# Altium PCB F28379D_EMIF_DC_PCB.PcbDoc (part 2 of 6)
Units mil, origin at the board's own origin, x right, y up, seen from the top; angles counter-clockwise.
Board outline 3000 x 1480 mil, 6 copper layers (Top Layer, Signal Layer 1, Signal Layer 2, Signal Layer 3, Signal Layer 4, Bottom Layer), stack 61.4 mil thick; 51 components, 68 nets, 414 pads, 205 vias.
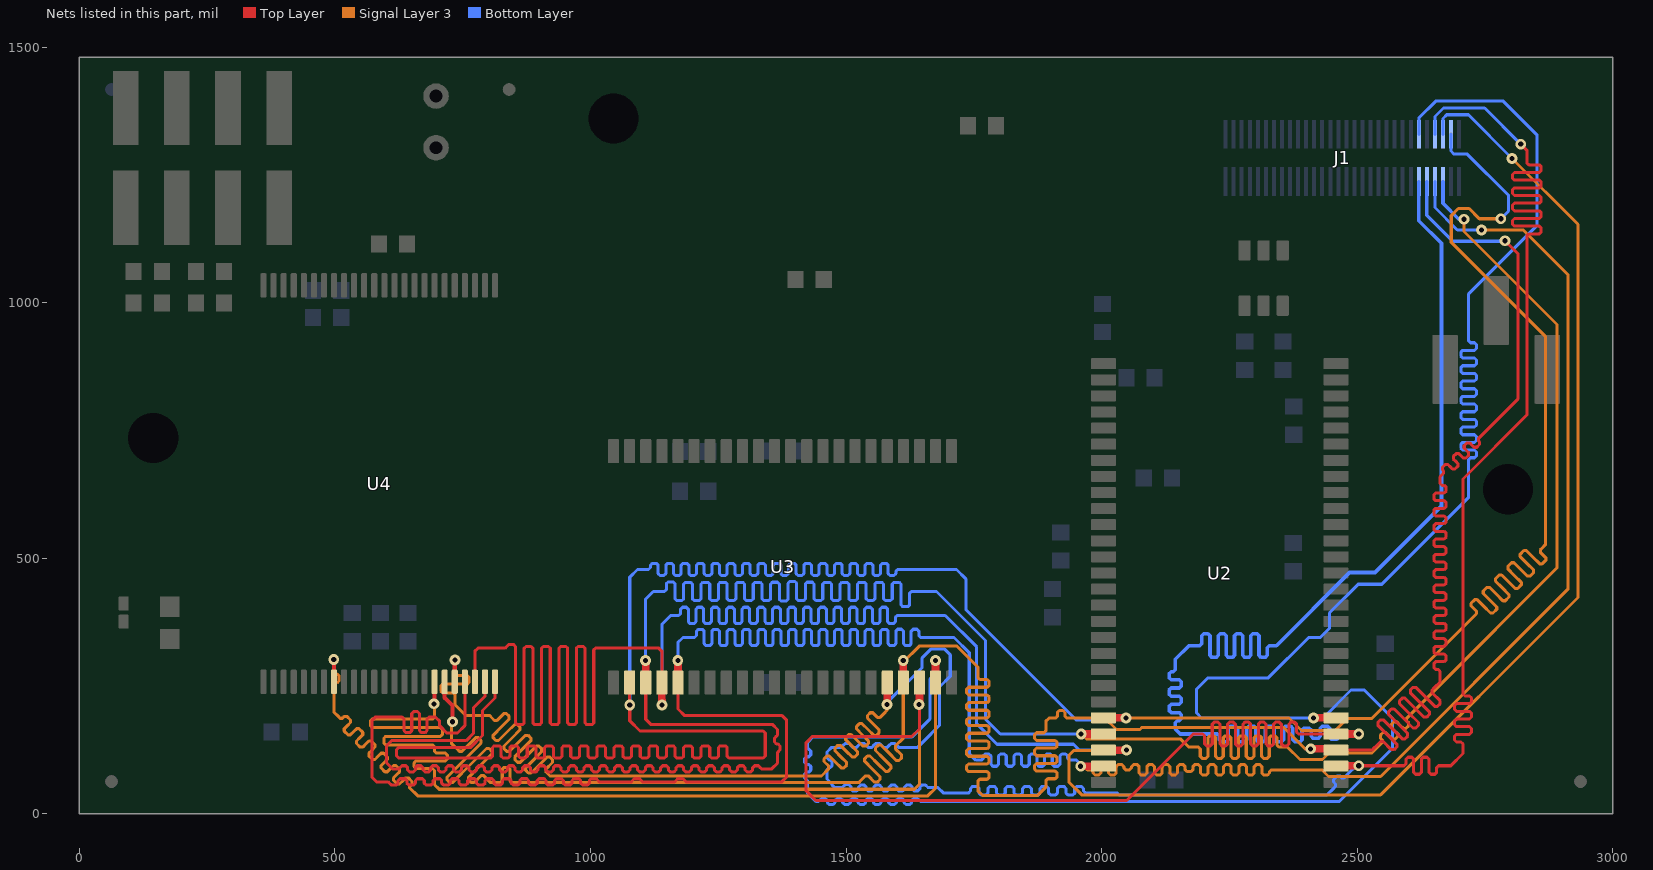
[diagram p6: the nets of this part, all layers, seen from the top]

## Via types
v1: diameter 21, hole 10, Top Layer to Bottom Layer, 204 vias
v2: diameter 20, hole 10, Top Layer to Bottom Layer, 1 vias

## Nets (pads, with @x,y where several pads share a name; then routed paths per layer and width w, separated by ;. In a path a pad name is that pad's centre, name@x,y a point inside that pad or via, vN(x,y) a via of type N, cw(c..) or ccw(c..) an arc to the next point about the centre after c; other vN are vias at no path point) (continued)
EM_A0: J1.4@2683.6,1329.26 U2.23 U3.2 U4.24 | length 6472.3
  Top Layer w6: U4.24@813.38,258.2 813.38,226.38 789,202 789,153 766,130 625,130 620.5,125.5 620.5,113.5 625,109 800,109 805.1,109 808.5,112.4 808.5,129.6 811.9,133 822.1,133 825.5,129.6 825.5,112.4 828.9,109 839.1,109 842.5,112.4 842.5,129.6 845.9,133 856.1,133 859.5,129.6 859.5,112.4 862.9,109 873.1,109 876.5,112.4 876.5,129.6 879.9,133 890.1,133 893.5,129.6 893.5,112.4 896.9,109 907.1,109 910.5,112.4 910.5,129.6 913.9,133 924.1,133 927.5,129.6 927.5,112.4 930.9,109 941.1,109 944.5,112.4 944.5,129.6 947.9,133 958.1,133 961.5,129.6 961.5,112.4 964.9,109 975.1,109 978.5,112.4 978.5,129.6 981.9,133 992.1,133 995.5,129.6 995.5,112.4 998.9,109 1009.1,109 1012.5,112.4 1012.5,129.6 1015.9,133 1026.1,133 1029.5,129.6 1029.5,112.4 1032.9,109 1043.1,109 1046.5,112.4 1046.5,129.6 1049.9,133 1060.1,133 1063.5,129.6 1063.5,112.4 1066.9,109 1077.1,109 1080.5,112.4 1080.5,129.6 1083.9,133 1094.1,133 1097.5,129.6 1097.5,112.4 1100.9,109 1111.1,109 1114.5,112.4 1114.5,129.6 1117.9,133 1128.1,133 1131.5,129.6 1131.5,112.4 1134.9,109 1145.1,109 1148.5,112.4 1148.5,129.6 1151.9,133 1162.1,133 1165.5,129.6 1165.5,112.4 1168.9,109 1179.1,109 1182.5,112.4 1182.5,129.6 1185.9,133 1196.1,133 1199.5,129.6 1199.5,112.4 1202.9,109 1213.1,109 1216.5,112.4 1216.5,129.6 1219.9,133 1230.1,133 1233.5,129.6 1233.5,112.4 1236.9,109 1247.1,109 1250.5,112.4 1250.5,129.6 1253.9,133 1264.1,133 1267.5,129.6 1267.5,112.4 1270.9,109 1271,109 1338,109 1342,113 1342,158 1338,162 1097,162 1077,182 v1(1077,213) v1@1077,217 ; v1@1076.79,217 U3.2@1076.79,256.62
  Top Layer w15: U2.23@2003.64,187.54 v1(2047.54,187.54)
  Signal Layer 3 w6: v1(2047.54,187.54) 2366.46,187.54 2391,163 2457,163 2480,186 2528,186 2702.5,360.5 2733.38,391.38 2733.38,396.19 2722.62,406.94 2722.62,411.75 2729.83,418.96 2734.64,418.96 2747.8,405.8 2760.96,392.64 2765.77,392.64 2772.99,399.85 2772.99,404.66 2759.82,417.82 2746.66,430.99 2746.66,435.79 2753.87,443.01 2758.68,443.01 2771.84,429.84 2785.01,416.68 2789.81,416.68 2797.03,423.89 2797.03,428.7 2783.86,441.86 2770.7,455.03 2770.7,459.84 2777.91,467.05 2782.72,467.05 2795.89,453.89 2809.05,440.72 2813.86,440.72 2821.07,447.94 2821.07,452.74 2807.91,465.91 2794.74,479.07 2794.74,483.88 2801.96,491.09 2806.76,491.09 2819.93,477.93 2833.09,464.77 2837.9,464.77 2845.11,471.98 2845.11,476.79 2831.95,489.95 2818.79,503.11 2818.79,507.92 2826,515.13 2830.81,515.13 2843.97,501.97 2857.13,488.81 2861.94,488.81 2869.15,496.02 2869.15,500.83 2858.39,511.59 2858.39,516.39 2862,520 2868,526 2868,934 2684,1118 2684,1170 2698,1184 2719,1184 2739,1164 v1(2781,1164)
  Bottom Layer w6: v1@1077,222 1077,463 1092,478 1110,478 1113.75,478 1117.5,481.75 1117.5,486.25 1121.25,490 1128.75,490 1132.5,486.25 1132.5,478 1132.5,469.75 1136.25,466 1143.75,466 1147.5,469.75 1147.5,478 1147.5,486.25 1151.25,490 1158.75,490 1162.5,486.25 1162.5,478 1162.5,469.75 1166.25,466 1173.75,466 1177.5,469.75 1177.5,478 1177.5,486.25 1181.25,490 1188.75,490 1192.5,486.25 1192.5,478 1192.5,469.75 1196.25,466 1203.75,466 1207.5,469.75 1207.5,478 1207.5,486.25 1211.25,490 1218.75,490 1222.5,486.25 1222.5,478 1222.5,469.75 1226.25,466 1233.75,466 1237.5,469.75 1237.5,478 1237.5,486.25 1241.25,490 1248.75,490 1252.5,486.25 1252.5,478 1252.5,469.75 1256.25,466 1263.75,466 1267.5,469.75 1267.5,478 1267.5,486.25 1271.25,490 1278.75,490 1282.5,486.25 1282.5,478 1282.5,469.75 1286.25,466 1293.75,466 1297.5,469.75 1297.5,478 1297.5,486.25 1301.25,490 1308.75,490 1312.5,486.25 1312.5,478 1312.5,469.75 1316.25,466 1323.75,466 1327.5,469.75 1327.5,478 1327.5,486.25 1331.25,490 1338.75,490 1342.5,486.25 1342.5,478 1342.5,469.75 1346.25,466 1353.75,466 1357.5,469.75 1357.5,478 1357.5,486.25 1361.25,490 1368.75,490 1372.5,486.25 1372.5,478 1372.5,469.75 1376.25,466 1383.75,466 1387.5,469.75 1387.5,478 1387.5,486.25 1391.25,490 1398.75,490 1402.5,486.25 1402.5,478 1402.5,469.75 1406.25,466 1413.75,466 1417.5,469.75 1417.5,478 1417.5,486.25 1421.25,490 1428.75,490 1432.5,486.25 1432.5,478 1432.5,469.75 1436.25,466 1443.75,466 1447.5,469.75 1447.5,478 1447.5,486.25 1451.25,490 1458.75,490 1462.5,486.25 1462.5,478 1462.5,469.75 1466.25,466 1473.75,466 1477.5,469.75 1477.5,478 1477.5,486.25 1481.25,490 1488.75,490 1492.5,486.25 1492.5,478 1492.5,469.75 1496.25,466 1503.75,466 1507.5,469.75 1507.5,478 1507.5,486.25 1511.25,490 1518.75,490 1522.5,486.25 1522.5,478 1522.5,469.75 1526.25,466 1533.75,466 1537.5,469.75 1537.5,478 1537.5,486.25 1541.25,490 1548.75,490 1552.5,486.25 1552.5,478 1552.5,469.75 1556.25,466 1563.75,466 1567.5,469.75 1567.5,478 1567.5,486.25 1571.25,490 1578.75,490 1582.5,486.25 1582.5,478 1582.5,469.75 1586.25,466 1593.75,466 1597.5,469.75 1597.5,474.25 1601.25,478 1665,478 1716,478 1734.5,459.5 1734.5,399.5 1950,184 1985,184 1988.54,187.54 v1(2047.54,187.54) ; J1.4@2683.6,1329.26 2683.6,1296.4 2689.5,1290.5 2715.5,1290.5 2796,1210 2796,1179 v1(2781,1164)
EM_A1: J1.5@2667.85,1236.74 U2.24 U3.3 U4.23 | length 6474.8
  Top Layer w6: U4.23@793.69,258.2 793.69,229.69 771,207 771,157 757,143 611,143 601,133 601,100 613,88 620,88 625.25,88 627.5,90.25 631.25,94 638.75,94 642.5,90.25 642.5,88 642.5,85.75 646.25,82 653.75,82 657.5,85.75 657.5,88 657.5,90.25 661.25,94 668.75,94 672.5,90.25 672.5,88 672.5,85.75 676.25,82 683.75,82 687.5,85.75 687.5,88 687.5,90.25 691.25,94 698.75,94 702.5,90.25 702.5,88 702.5,85.75 706.25,82 713.75,82 717.5,85.75 717.5,88 717.5,90.25 721.25,94 728.75,94 732.5,90.25 732.5,88 732.5,85.75 736.25,82 743.75,82 747.5,85.75 747.5,88 747.5,90.25 751.25,94 758.75,94 762.5,90.25 762.5,88 762.5,85.75 766.25,82 773.75,82 777.5,85.75 777.5,88 777.5,90.25 781.25,94 788.75,94 792.5,90.25 792.5,88 792.5,85.75 796.25,82 803.75,82 807.5,85.75 807.5,88 807.5,90.25 811.25,94 818.75,94 822.5,90.25 822.5,88 822.5,85.75 826.25,82 833.75,82 837.5,85.75 837.5,88 837.5,90.25 841.25,94 848.75,94 852.5,90.25 852.5,88 852.5,85.75 856.25,82 863.75,82 867.5,85.75 867.5,88 867.5,90.25 871.25,94 878.75,94 882.5,90.25 882.5,88 882.5,85.75 886.25,82 893.75,82 897.5,85.75 897.5,88 897.5,90.25 901.25,94 908.75,94 912.5,90.25 912.5,88 912.5,85.75 916.25,82 923.75,82 927.5,85.75 927.5,88 927.5,90.25 931.25,94 938.75,94 942.5,90.25 942.5,88 942.5,85.75 946.25,82 953.75,82 957.5,85.75 957.5,88 957.5,90.25 961.25,94 968.75,94 972.5,90.25 972.5,88 972.5,85.75 976.25,82 983.75,82 987.5,85.75 987.5,88 987.5,90.25 991.25,94 998.75,94 1002.5,90.25 1002.5,88 1002.5,85.75 1006.25,82 1013.75,82 1017.5,85.75 1017.5,88 1017.5,90.25 1021.25,94 1028.75,94 1032.5,90.25 1032.5,88 1032.5,85.75 1036.25,82 1043.75,82 1047.5,85.75 1047.5,88 1047.5,90.25 1051.25,94 1058.75,94 1062.5,90.25 1062.5,88 1062.5,85.75 1066.25,82 1073.75,82 1077.5,85.75 1077.5,88 1077.5,90.25 1081.25,94 1088.75,94 1092.5,90.25 1092.5,88 1092.5,85.75 1096.25,82 1103.75,82 1107.5,85.75 1107.5,88 1107.5,90.25 1111.25,94 1118.75,94 1122.5,90.25 1122.5,88 1122.5,85.75 1126.25,82 1133.75,82 1137.5,85.75 1137.5,88 1137.5,90.25 1141.25,94 1148.75,94 1152.5,90.25 1152.5,88 1152.5,85.75 1156.25,82 1163.75,82 1167.5,85.75 1167.5,88 1167.5,90.25 1171.25,94 1178.75,94 1182.5,90.25 1182.5,88 1182.5,85.75 1186.25,82 1193.75,82 1197.5,85.75 1197.5,88 1197.5,90.25 1201.25,94 1208.75,94 1212.5,90.25 1212.5,88 1212.5,85.75 1216.25,82 1223.75,82 1227.5,85.75 1227.5,88 1227.5,90.25 1231.25,94 1238.75,94 1242.5,90.25 1242.5,88 1242.5,85.75 1246.25,82 1253.75,82 1257.5,85.75 1257.5,88 1257.5,90.25 1261.25,94 1268.75,94 1272.5,90.25 1272.5,88 1272.5,85.75 1276.25,82 1283.75,82 1287.5,85.75 1287.5,88 1287.5,90.25 1291.25,94 1298.75,94 1302.5,90.25 1302.5,88 1302.5,85.75 1306.25,82 1313.75,82 1317.5,85.75 1317.5,88 1317.5,90.25 1321.25,94 1328.75,94 1332.5,90.25 1334.75,88 1347.5,88 1355,88 1366,99 1366,106.5 1366,120.25 1367.25,121.5 1371,125.25 1371,132.75 1367.25,136.5 1366,136.5 1363.75,136.5 1360,140.25 1360,147.75 1363.75,151.5 1366,153.75 1366,165 1356,175 1348.5,175 1333.5,175 1321,175 1118,175 1108.28,184.72 U3.3@1108.28,256.62
  Top Layer w15: U3.3@1108.28,256.62 v1@1108.28,290.72 ; v1@1961.96,156.04 U2.24@2003.64,156.04
  Signal Layer 3 w6: v1@1961.96,156.04 1972,146 2155.04,146 2170.52,130.52 2178.02,130.52 2189.27,130.52 2193.02,126.77 2193.02,112.27 2196.77,108.52 2204.27,108.52 2208.02,112.27 2208.02,130.52 2208.02,148.77 2211.77,152.52 2219.27,152.52 2223.02,148.77 2223.02,130.52 2223.02,112.27 2226.77,108.52 2234.27,108.52 2238.02,112.27 2238.02,130.52 2238.02,148.77 2241.77,152.52 2249.27,152.52 2253.02,148.77 2253.02,130.52 2253.02,112.27 2256.77,108.52 2264.27,108.52 2268.02,112.27 2268.02,130.52 2268.02,148.77 2271.77,152.52 2279.27,152.52 2283.02,148.77 2283.02,130.52 2283.02,112.27 2286.77,108.52 2294.27,108.52 2298.02,112.27 2298.02,130.52 2298.02,148.77 2301.77,152.52 2309.27,152.52 2313.02,148.77 2313.02,130.52 2313.02,112.27 2316.77,108.52 2324.27,108.52 2328.02,112.27 2328.02,130.52 2328.02,148.77 2331.77,152.52 2339.27,152.52 2343.02,148.77 2343.02,134.27 2346.77,130.52 2363.48,130.52 2388,106 2432,106 2445,119 2529,119 2546.5,136.5 2549.15,139.15 2549.15,144.45 2545.37,148.24 2545.37,153.54 2550.67,158.85 2555.97,158.85 2562.41,152.41 2568.85,145.97 2574.15,145.97 2579.45,151.28 2579.45,156.58 2573.02,163.02 2566.58,169.45 2566.58,174.76 2571.88,180.06 2577.19,180.06 2583.62,173.62 2590.06,167.19 2595.36,167.19 2600.67,172.49 2600.67,177.79 2596.88,181.58 2596.88,186.88 2651.5,241.5 2891,481 2891,957 2709,1139 v1(2709,1163) v1@2709,1164
  Bottom Layer w6: v1@1108,297 v1(1108,300) 1108,420 1123,435 1140,435 1145.1,435 1148.5,438.4 1148.5,450.01 1151.9,453.41 1162.1,453.41 1165.5,450.01 1165.5,435 1165.5,420.61 1168.9,417.21 1179.1,417.21 1182.5,420.61 1182.5,435 1182.5,449.33 1185.9,452.73 1196.1,452.73 1199.5,449.33 1199.5,435 1199.5,420.66 1202.9,417.26 1213.1,417.26 1216.5,420.66 1216.5,435 1216.5,449.33 1219.9,452.73 1230.1,452.73 1233.5,449.33 1233.5,435 1233.5,420.66 1236.9,417.26 1247.1,417.26 1250.5,420.66 1250.5,435 1250.5,449.33 1253.9,452.73 1264.1,452.73 1267.5,449.33 1267.5,435 1267.5,420.66 1270.9,417.26 1281.1,417.26 1284.5,420.66 1284.5,435 1284.5,449.33 1287.9,452.73 1298.1,452.73 1301.5,449.33 1301.5,435 1301.5,420.66 1304.9,417.26 1315.1,417.26 1318.5,420.66 1318.5,435 1318.5,449.33 1321.9,452.73 1332.1,452.73 1335.5,449.33 1335.5,435 1335.5,420.61 1338.9,417.21 1349.1,417.21 1352.5,420.61 1352.5,435 1352.5,449.51 1355.9,452.91 1366.1,452.91 1369.5,449.51 1369.5,435 1369.5,419.59 1372.9,416.19 1383.1,416.19 1386.5,419.59 1386.5,435 1386.5,450.88 1389.9,454.28 1400.1,454.28 1403.5,450.88 1403.5,435 1403.5,420.27 1406.9,416.87 1417.1,416.87 1420.5,420.27 1420.5,435 1420.5,449.51 1423.9,452.91 1434.1,452.91 1437.5,449.51 1437.5,435 1437.5,420.66 1440.9,417.26 1451.1,417.26 1454.5,420.66 1454.5,435 1454.5,449.33 1457.9,452.73 1468.1,452.73 1471.5,449.33 1471.5,435 1471.5,420.66 1474.9,417.26 1485.1,417.26 1488.5,420.66 1488.5,435 1488.5,449.33 1491.9,452.73 1502.1,452.73 1505.5,449.33 1505.5,435 1505.5,420.66 1508.9,417.26 1519.1,417.26 1522.5,420.66 1522.5,435 1522.5,449.33 1525.9,452.73 1536.1,452.73 1539.5,449.33 1539.5,435 1539.5,420.66 1542.9,417.26 1553.1,417.26 1556.5,420.66 1556.5,435 1556.5,449.33 1559.9,452.73 1570.1,452.73 1573.5,449.33 1573.5,435 1573.5,420.66 1576.9,417.26 1587.1,417.26 1590.5,420.66 1590.5,435 1590.5,449.33 1593.9,452.73 1604.1,452.73 1607.5,449.33 1607.5,435 1607.5,408.67 1610.9,405.27 1621.1,405.27 1624.5,408.67 1624.5,431.6 1627.9,435 1644,435 1677,435 1773,339 1773,185 1801.96,156.04 v1(1959.96,156.04) v1@1961.96,156.04
  Bottom Layer w7: J1.5@2667.85,1236.74 2667.85,1194.15 2698,1164 v1@2709,1164
EM_A2: J1.6@2667.85,1329.26 U2.25 U3.4 U4.22 | length 6534.8
  Top Layer w6: U4.22@774.01,258.2 774.01,318.01 780,324 828,324 833.1,324 836.5,327.4 839.9,330.8 850.1,330.8 853.5,327.4 853.5,324 853.5,177.82 856.9,174.42 867.1,174.42 870.5,177.82 870.5,324 873.9,327.4 884.1,327.4 887.5,324 887.5,177.82 890.9,174.42 901.1,174.42 904.5,177.82 904.5,324 907.9,327.4 918.1,327.4 921.5,324 921.5,177.82 924.9,174.42 935.1,174.42 938.5,177.82 938.5,324 941.9,327.4 952.1,327.4 955.5,324 955.5,177.82 958.9,174.42 969.1,174.42 972.5,177.82 972.5,324 975.9,327.4 986.1,327.4 989.5,324 989.5,177.82 992.9,174.42 1003.1,174.42 1006.5,177.82 1006.5,320.6 1009.9,324 1035,324 1133.78,324 1139.78,318 U3.4@1139.78,256.62
  Top Layer w15: U3.4@1139.78,256.62 1139.78,222.22 v1@1140,222 ; U2.25@2003.64,124.54 v1@2044.54,124.54
  Signal Layer 3 w6: v1@2044.54,124.54 2044,124 1946,124 1936,114 1936,62 1961,37 2546,37 2932,423 2932,1153 v1(2803,1282) ; v1@2800,1280 v1@2800.5,1279.5
  Bottom Layer w6: v1@1140,222 1140,371 1157,388 1169,388 1172.75,388 1176.5,391.75 1176.5,400.24 1180.25,403.99 1187.75,403.99 1191.5,400.24 1191.5,388 1191.5,375.76 1195.25,372.01 1202.75,372.01 1206.5,375.76 1206.5,388 1206.5,400.24 1210.25,403.99 1217.75,403.99 1221.5,400.24 1221.5,388 1221.5,375.76 1225.25,372.01 1232.75,372.01 1236.5,375.76 1236.5,388 1236.5,400.24 1240.25,403.99 1247.75,403.99 1251.5,400.24 1251.5,388 1251.5,375.76 1255.25,372.01 1262.75,372.01 1266.5,375.76 1266.5,388 1266.5,400.24 1270.25,403.99 1277.75,403.99 1281.5,400.24 1281.5,388 1281.5,375.76 1285.25,372.01 1292.75,372.01 1296.5,375.76 1296.5,388 1296.5,400.24 1300.25,403.99 1307.75,403.99 1311.5,400.24 1311.5,388 1311.5,375.76 1315.25,372.01 1322.75,372.01 1326.5,375.76 1326.5,388 1326.5,400.24 1330.25,403.99 1337.75,403.99 1341.5,400.24 1341.5,388 1341.5,375.76 1345.25,372.01 1352.75,372.01 1356.5,375.76 1356.5,388 1356.5,400.24 1360.25,403.99 1367.75,403.99 1371.5,400.24 1371.5,388 1371.5,375.76 1375.25,372.01 1382.75,372.01 1386.5,375.76 1386.5,388 1386.5,400.24 1390.25,403.99 1397.75,403.99 1401.5,400.24 1401.5,388 1401.5,375.76 1405.25,372.01 1412.75,372.01 1416.5,375.76 1416.5,388 1416.5,400.24 1420.25,403.99 1427.75,403.99 1431.5,400.24 1431.5,388 1431.5,375.76 1435.25,372.01 1442.75,372.01 1446.5,375.76 1446.5,388 1446.5,400.24 1450.25,403.99 1457.75,403.99 1461.5,400.24 1461.5,388 1461.5,375.76 1465.25,372.01 1472.75,372.01 1476.5,375.76 1476.5,388 1476.5,400.24 1480.25,403.99 1487.75,403.99 1491.5,400.24 1491.5,388 1491.5,375.76 1495.25,372.01 1502.75,372.01 1506.5,375.76 1506.5,388 1506.5,400.24 1510.25,403.99 1517.75,403.99 1521.5,400.24 1521.5,388 1521.5,375.76 1525.25,372.01 1532.75,372.01 1536.5,375.76 1536.5,388 1536.5,400.24 1540.25,403.99 1547.75,403.99 1551.5,400.24 1551.5,388 1551.5,375.76 1555.25,372.01 1562.75,372.01 1566.5,375.76 1566.5,388 1566.5,400.24 1570.25,403.99 1577.75,403.99 1581.5,400.24 1581.5,388 1581.5,375.76 1585.25,372.01 1592.75,372.01 1596.5,375.76 1596.5,384.25 1600.25,388 1679,388 1694,388 1755.5,326.5 1755.5,176 1795.5,136 1945,136 1956.46,124.54 v1@2044.54,124.54 ; J1.6@2667.85,1329.26 2667.85,1360 2675.26,1367.41 2717.59,1367.41 v1(2803,1282)
  other v1: 2048.54,124.54 1140,213
EM_A3: J1.7@2652.1,1236.74 U2.26 U3.5 U4.21 | length 6473.9
  Top Layer w6: U4.21@754.32,258.2 754.32,172.32 740,158 719,158 705,172 705,181 697,189 688,189 684.25,189 680.5,185.25 680.5,162.51 676.75,158.76 669.25,158.76 665.5,162.51 665.5,189 665.5,196.04 661.75,199.79 654.25,199.79 650.5,196.04 650.5,189 650.5,162.51 646.75,158.76 639.25,158.76 635.5,162.51 635.5,185.25 631.75,189 579,189 573,183 573,71 581.5,62.5 590,62.5 604.4,62.5 607,59.9 610.4,56.5 620.6,56.5 624,59.9 624,62.5 624,65.1 627.4,68.5 637.6,68.5 641,65.1 641,62.5 641,59.9 644.4,56.5 654.6,56.5 658,59.9 658,62.5 658,65.1 661.4,68.5 671.6,68.5 675,65.1 675,62.5 675,59.9 678.4,56.5 688.6,56.5 692,59.9 692,62.5 692,65.1 695.4,68.5 705.6,68.5 709,65.1 709,62.5 709,59.9 712.4,56.5 722.6,56.5 726,59.9 726,62.5 726,65.1 729.4,68.5 739.6,68.5 743,65.1 743,62.5 743,59.9 746.4,56.5 756.6,56.5 760,59.9 760,62.5 760,65.1 763.4,68.5 773.6,68.5 777,65.1 777,62.5 777,59.9 780.4,56.5 790.6,56.5 794,59.9 794,62.5 794,65.1 797.4,68.5 807.6,68.5 811,65.1 811,62.5 811,59.9 814.4,56.5 824.6,56.5 828,59.9 828,62.5 828,65.1 831.4,68.5 841.6,68.5 845,65.1 845,62.5 845,59.9 848.4,56.5 858.6,56.5 862,59.9 862,62.5 862,65.1 865.4,68.5 875.6,68.5 879,65.1 879,62.5 879,59.9 882.4,56.5 892.6,56.5 896,59.9 896,62.5 896,65.1 899.4,68.5 909.6,68.5 913,65.1 913,62.5 913,59.9 916.4,56.5 926.6,56.5 930,59.9 930,62.5 930,65.1 933.4,68.5 943.6,68.5 947,65.1 947,62.5 947,59.9 950.4,56.5 960.6,56.5 964,59.9 964,62.5 964,65.1 967.4,68.5 977.6,68.5 981,65.1 981,62.5 981,59.9 984.4,56.5 994.6,56.5 998,59.9 998,62.5 998,65.1 1001.4,68.5 1011.6,68.5 1015,65.1 1017.6,62.5 1053,62.5 1074,62.5 1079.9,62.5 1082.5,65.1 1085.9,68.5 1096.1,68.5 1099.5,65.1 1102.1,62.5 1151,62.5 1159,62.5 1164.9,62.5 1167.5,65.1 1170.9,68.5 1181.1,68.5 1184.5,65.1 1187.1,62.5 1218,62.5 1374.5,62.5 1384,72 1384,183 1375,192 1184.28,192 1171.28,205 U3.5@1171.28,256.62
  Top Layer w15: v1@1171,291 1171.28,290.72 U3.5@1171.28,256.62 ; v1@1963.05,93.05 U2.26@2003.64,93.05
  Signal Layer 3 w6: v1@1963.05,93.05 v1@1964.05,92.05 ; v1@1965.05,93.05 1972.1,86 1979.75,86 1983.5,82.25 1983.5,79.75 1987.25,76 1994.75,76 1998.5,79.75 1998.5,86 1998.5,92.25 2002.25,96 2009.75,96 2013.5,92.25 2013.5,86 2013.5,79.75 2017.25,76 2024.75,76 2028.5,79.75 2028.5,86 2028.5,92.25 2032.25,96 2039.75,96 2043.5,92.25 2043.5,89.75 2047.25,86 2054.75,86 2058.5,89.75 2058.5,92.25 2062.25,96 2069.75,96 2073.5,92.25 2073.5,86 2073.5,79.75 2077.25,76 2084.75,76 2088.5,79.75 2088.5,86 2088.5,92.25 2092.25,96 2099.75,96 2103.5,92.25 2103.5,86 2103.5,79.75 2107.25,76 2114.75,76 2118.5,79.75 2118.5,86 2118.5,92.25 2122.25,96 2129.75,96 2133.5,92.25 2133.5,86 2133.5,79.75 2137.25,76 2144.75,76 2148.5,79.75 2148.5,86 2148.5,92.25 2152.25,96 2159.75,96 2163.5,92.25 2163.5,86 2166.67,82.83 2175.33,82.83 2178.5,86 2178.5,92.25 2182.25,96 2189.75,96 2193.5,92.25 2193.5,86 2193.5,79.75 2197.25,76 2204.75,76 2208.5,79.75 2208.5,86 2208.5,92.25 2212.25,96 2219.75,96 2223.5,92.25 2223.5,86 2223.5,79.75 2227.25,76 2234.75,76 2238.5,79.75 2238.5,86 2238.5,92.25 2242.25,96 2249.75,96 2253.5,92.25 2253.5,86 2253.5,79.75 2257.25,76 2264.75,76 2268.5,79.75 2268.5,86 2268.5,92.25 2272.25,96 2279.75,96 2283.5,92.25 2283.5,86 2283.5,79.75 2287.25,76 2294.75,76 2298.5,79.75 2298.5,86 2298.5,92.25 2302.25,96 2309.75,96 2313.5,92.25 2313.5,86 2313.5,79.75 2317.25,76 2324.75,76 2328.5,79.75 2328.5,82.25 2332.25,86 2336,86 2431.05,86 2444.05,73 2545.95,73 2912,439.05 2912,1055 2825,1142 v1(2743,1142)
  Bottom Layer w6: v1@1171,297 v1(1171,300) 1171,335 1181,345 1200,345 1203.75,345 1207.5,348.75 1207.5,357.01 1211.25,360.76 1218.75,360.76 1222.5,357.01 1222.5,345 1222.5,332.75 1226.25,329 1233.75,329 1237.5,332.75 1237.5,345 1237.5,357.01 1241.25,360.76 1248.75,360.76 1252.5,357.01 1252.5,345 1252.5,332.75 1256.25,329 1263.75,329 1267.5,332.75 1267.5,345 1267.5,357.01 1271.25,360.76 1278.75,360.76 1282.5,357.01 1282.5,345 1282.5,332.75 1286.25,329 1293.75,329 1297.5,332.75 1297.5,345 1297.5,357.01 1301.25,360.76 1308.75,360.76 1312.5,357.01 1312.5,345 1312.5,332.75 1316.25,329 1323.75,329 1327.5,332.75 1327.5,345 1327.5,357.01 1331.25,360.76 1338.75,360.76 1342.5,357.01 1342.5,345 1342.5,332.75 1346.25,329 1353.75,329 1357.5,332.75 1357.5,345 1357.5,357.01 1361.25,360.76 1368.75,360.76 1372.5,357.01 1372.5,345 1372.5,332.75 1376.25,329 1383.75,329 1387.5,332.75 1387.5,345 1387.5,357.01 1391.25,360.76 1398.75,360.76 1402.5,357.01 1402.5,345 1402.5,332.75 1406.25,329 1413.75,329 1417.5,332.75 1417.5,345 1417.5,357.01 1421.25,360.76 1428.75,360.76 1432.5,357.01 1432.5,345 1432.5,332.75 1436.25,329 1443.75,329 1447.5,332.75 1447.5,345 1447.5,357.01 1451.25,360.76 1458.75,360.76 1462.5,357.01 1462.5,345 1462.5,332.75 1466.25,329 1473.75,329 1477.5,332.75 1477.5,345 1477.5,357.01 1481.25,360.76 1488.75,360.76 1492.5,357.01 1492.5,345 1492.5,332.75 1496.25,329 1503.75,329 1507.5,332.75 1507.5,345 1507.5,357.01 1511.25,360.76 1518.75,360.76 1522.5,357.01 1522.5,345 1522.5,332.75 1526.25,329 1533.75,329 1537.5,332.75 1537.5,345 1537.5,357.01 1541.25,360.76 1548.75,360.76 1552.5,357.01 1552.5,345 1552.5,332.75 1556.25,329 1563.75,329 1567.5,332.75 1567.5,345 1567.5,357.01 1571.25,360.76 1578.75,360.76 1582.5,357.01 1582.5,345 1582.5,332.75 1586.25,329 1593.75,329 1597.5,332.75 1597.5,345 1597.5,357.25 1601.25,361 1608.75,361 1612.5,357.25 1612.5,345 1612.5,332.75 1616.25,329 1623.75,329 1627.5,332.75 1627.5,345 1627.5,357.25 1631.25,361 1638.75,361 1642.5,357.25 1642.5,348.75 1646.25,345 1693,345 1711.1,345 1741.1,315 1741.1,117.9 1754,105 1761,105 1764.75,105 1768.5,108.75 1768.5,113.25 1772.25,117 1779.75,117 1783.5,113.25 1783.5,105 1783.5,96.75 1787.25,93 1794.75,93 1798.5,96.75 1798.5,105 1798.5,113.25 1802.25,117 1809.75,117 1813.5,113.25 1813.5,105 1813.5,96.75 1817.25,93 1824.75,93 1828.5,96.75 1828.5,105 1828.5,113.25 1832.25,117 1839.75,117 1843.5,113.25 1843.5,105 1843.5,96.75 1847.25,93 1854.75,93 1858.5,96.75 1858.5,105 1858.5,113.25 1862.25,117 1869.75,117 1873.5,113.25 1873.5,105 1873.5,96.75 1877.25,93 1884.75,93 1888.5,96.75 1888.5,105 1888.5,113.25 1892.25,117 1899.75,117 1903.5,113.25 1903.5,105 1903.5,96.75 1907.25,93 1914.75,93 1918.5,96.75 1918.5,105 1918.5,113.25 1922.25,117 1929.75,117 1933.5,113.25 1933.5,108.75 1937.25,105 1951,105 1951.1,105 v1@1963.05,93.05 ; J1.7@2652.1,1236.74 2652.1,1185.9 2696,1142 v1(2743,1142)
  other v1: 1959.05,93.05
EM_A4: J1.8@2652.1,1329.26 U2.29 U3.18 U4.20 | length 6436.5
  Top Layer w6: v1@2498,94 v1(2503,94) 2588,94 2591.75,94 2595.5,97.75 2595.5,106.87 2599.25,110.62 2606.75,110.62 2610.5,106.87 2610.5,94 2610.5,81.13 2614.25,77.38 2621.75,77.38 2625.5,81.13 2625.5,94 2625.5,106.87 2629.25,110.62 2636.75,110.62 2640.5,106.87 2640.5,94 2640.5,81.13 2644.25,77.38 2651.75,77.38 2655.5,81.13 2655.5,90.25 2659.25,94 2670.5,94 2683,94 2707,118 2707,125.5 2707,136.75 2703.25,140.5 2694.13,140.5 2690.38,144.25 2690.38,151.75 2694.13,155.5 2707,155.5 2719.87,155.5 2723.62,159.25 2723.62,166.75 2719.87,170.5 2707,170.5 2694.13,170.5 2690.38,174.25 2690.38,181.75 2694.13,185.5 2707,185.5 2719.87,185.5 2723.62,189.25 2723.62,196.75 2719.87,200.5 2707,200.5 2694.13,200.5 2690.38,204.25 2690.38,211.75 2694.13,215.5 2707,215.5 2719.87,215.5 2723.62,219.25 2723.62,226.75 2719.87,230.5 2710.75,230.5 2707,234.25 2707,276 2707,655 2832,780 2832,1123 2832,1130.75 2835.75,1134.5 2856.25,1134.5 2860,1138.25 2860,1145.75 2856.25,1149.5 2832,1149.5 2807.75,1149.5 2804,1153.25 2804,1160.75 2807.75,1164.5 2832,1164.5 2856.25,1164.5 2860,1168.25 2860,1175.75 2856.25,1179.5 2832,1179.5 2807.75,1179.5 2804,1183.25 2804,1190.75 2807.75,1194.5 2832,1194.5 2856.25,1194.5 2860,1198.25 2860,1205.75 2856.25,1209.5 2832,1209.5 2807.75,1209.5 2804,1213.25 2804,1220.75 2807.75,1224.5 2832,1224.5 2856.25,1224.5 2860,1228.25 2860,1235.75 2856.25,1239.5 2832,1239.5 2807.75,1239.5 2804,1243.25 2804,1250.75 2807.75,1254.5 2832,1254.5 2856.25,1254.5 2860,1258.25 2860,1265.75 2856.25,1269.5 2835.75,1269.5 2832,1273.25 2832,1277 2832,1298 v1(2820,1310)
  Top Layer w8: U4.20@734.64,258.2 734.64,297.64 v1@735,298
  Top Layer w15: v1@1580.72,222.72 U3.18@1580.72,256.62 ; U2.29@2458.36,93.05 2460.41,91 2463.41,94 v1@2498,94
  Signal Layer 3 w6: v1@735,298 735,279 735,273.9 738.4,270.5 759.07,270.5 762.47,267.1 762.47,256.9 759.07,253.5 735,253.5 710.93,253.5 707.53,250.1 707.53,239.9 710.93,236.5 731.6,236.5 735,233.1 735,220 735,213 755.5,192.5 802.5,192.5 809.5,185.5 812.15,182.85 817.45,182.85 830.54,195.93 835.84,195.93 841.14,190.63 841.14,185.32 825.41,169.59 809.68,153.86 809.68,148.55 814.98,143.25 820.28,143.25 836.02,158.98 851.75,174.72 857.05,174.72 862.36,169.41 862.36,164.11 846.62,148.38 830.89,132.64 830.89,127.34 836.19,122.04 841.5,122.04 857.23,137.77 872.96,153.5 878.27,153.5 883.57,148.2 883.57,142.9 867.84,127.16 852.1,111.43 852.1,106.13 857.41,100.82 862.71,100.82 878.44,116.56 894.18,132.29 899.48,132.29 904.78,126.99 904.78,121.68 889.05,105.95 873.32,90.22 873.32,84.91 878.62,79.61 883.92,79.61 899.66,95.34 915.39,111.08 920.69,111.08 926,105.77 926,100.47 912.91,87.39 912.91,82.09 915,80 921,74 1431,74 1444.5,74 1452,74 1465.98,87.98 1465.98,93.28 1457.14,102.12 1457.14,107.42 1462.44,112.73 1467.75,112.73 1479.24,101.24 1490.73,89.75 1496.03,89.75 1501.33,95.05 1501.33,100.35 1489.84,111.84 1478.35,123.33 1478.35,128.64 1483.66,133.94 1488.96,133.94 1500.45,122.45 1511.94,110.96 1517.24,110.96 1522.55,116.26 1522.55,121.57 1511.06,133.06 1499.57,144.55 1499.57,149.85 1504.87,155.15 1510.17,155.15 1521.66,143.66 1533.15,132.17 1538.46,132.17 1543.76,137.48 1543.76,142.78 1532.27,154.27 1520.78,165.76 1520.78,171.06 1526.08,176.37 1531.39,176.37 1542.88,164.88 1554.37,153.39 1559.67,153.39 1564.97,158.69 1564.97,163.99 1553.48,175.48 1541.99,186.97 1541.99,192.28 1547.3,197.58 1552.6,197.58 1561.44,188.74 1566.74,188.74 1574.7,196.7 1580,202 v1(1580,214) v1@1580,217
  Bottom Layer w6: v1@1580,217 1649,286 1649,305 1666,322 1693,322 1704,311 1704,269 1683,248 1683,173 1651,141 1645.3,135.3 1640,130 1629.5,130 1614.5,130 1603.25,130 1599.5,133.75 1595.75,137.5 1588.25,137.5 1584.5,133.75 1580.75,130 1573.25,130 1569.5,133.75 1565.75,137.5 1558.25,137.5 1554.5,133.75 1550.75,130 1543.25,130 1539.5,133.75 1535.75,137.5 1528.25,137.5 1524.5,133.75 1520.75,130 1513.25,130 1509.5,133.75 1505.75,137.5 1498.25,137.5 1494.5,133.75 1490.75,130 1479.5,130 1472,130 1463,121 1463,120.5 1463,109.25 1466.75,105.5 1469.25,105.5 1473,101.75 1473,94.25 1469.25,90.5 1466.75,90.5 1463,86.75 1463,75.5 1463,68 1473,58 1473,56 1478,51 1487,51 1492.25,51 1494.5,53.25 1498.25,57 1505.75,57 1509.5,53.25 1509.5,51 1509.5,48.75 1513.25,45 1520.75,45 1524.5,48.75 1524.5,51 1524.5,52.25 1528.25,56 1535.75,56 1539.5,52.25 1539.5,51 1539.5,48.75 1543.25,45 1550.75,45 1554.5,48.75 1554.5,51 1554.5,52.25 1558.25,56 1565.75,56 1569.5,52.25 1569.5,51 1569.5,48.75 1573.25,45 1580.75,45 1584.5,48.75 1584.5,51 1584.5,52.25 1588.25,56 1595.75,56 1599.5,52.25 1599.5,51 1599.5,48.75 1603.25,45 1610.75,45 1614.5,48.75 1614.5,51 1614.5,52.25 1618.25,56 1625.75,56 1629.5,52.25 1629.5,51 1629.5,48.75 1633.25,45 1640.75,45 1644.5,48.75 1644.5,51 1644.5,52.25 1648.25,56 1655.75,56 1659.5,52.25 1660.75,51 1674.5,51 1680,51 1690,41 1735,41 1740.1,41 1743.5,44.4 1743.5,49.6 1746.9,53 1757.1,53 1760.5,49.6 1760.5,41 1760.5,40.4 1763.9,37 1774.1,37 1777.5,40.4 1777.5,41 1777.5,49.6 1780.9,53 1791.1,53 1794.5,49.6 1794.5,41 1794.5,40.4 1797.9,37 1808.1,37 1811.5,40.4 1811.5,41 1811.5,49.6 1814.9,53 1825.1,53 1828.5,49.6 1828.5,41 1828.5,40.4 1831.9,37 1842.1,37 1845.5,40.4 1845.5,41 1845.5,49.6 1848.9,53 1859.1,53 1862.5,49.6 1862.5,41 1862.5,40.4 1865.9,37 1876.1,37 1879.5,40.4 1879.5,41 1879.5,49.6 1882.9,53 1893.1,53 1896.5,49.6 1896.5,41 1896.5,40.4 1899.9,37 1910.1,37 1913.5,40.4 1913.5,41 1913.5,49.6 1916.9,53 1927.1,53 1930.5,49.6 1930.5,41 1930.5,40.4 1933.9,37 1944.1,37 1947.5,40.4 1947.5,41 1947.5,49.6 1950.9,53 1961.1,53 1964.5,49.6 1964.5,44.4 1967.9,41 2019,41 2030,41 2034,37 2441,37 2454,50 2457.61,53.61 2457.61,58.41 2453.93,62.09 2453.93,66.9 2461.14,74.11 2465.95,74.11 2469.63,70.44 2474.44,70.44 2482,78 v1@2498,94 ; J1.8@2652.1,1329.26 2652.1,1364.1 2668.7,1380.7 2749.3,1380.7 v1(2820,1310)
  other v1: 735,301
EM_A5: J1.9@2636.35,1236.74 U2.30 U3.19 U4.19 | length 6400.8
  Top Layer w6: U2.30@2455.91,127 U2.30@2458.36,127 ; U2.30@2458.36,124.54 2529,124.54 2532.46,128 2537.76,133.3 2545.71,141.26 2551.02,141.26 2566.93,125.35 2572.23,125.35 2577.53,130.65 2577.53,135.95 2558.97,154.52 2540.41,173.08 2540.41,178.38 2545.71,183.68 2551.02,183.68 2569.58,165.12 2588.14,146.56 2593.44,146.56 2598.75,151.86 2598.75,157.17 2580.19,175.73 2561.62,194.29 2561.62,199.59 2566.93,204.9 2572.23,204.9 2590.79,186.34 2609.35,167.77 2614.66,167.77 2619.96,173.08 2619.96,178.38 2601.4,196.94 2582.84,215.5 2582.84,220.81 2588.14,226.11 2593.44,226.11 2612.01,207.55 2630.57,188.99 2635.87,188.99 2641.17,194.29 2641.17,199.59 2622.61,218.16 2604.05,236.72 2604.05,242.02 2609.35,247.32 2614.66,247.32 2633.22,228.76 2651.78,210.2 2657.08,210.2 2662.39,215.5 2662.39,220.81 2646.48,236.72 2646.48,242.02 2650.73,246.27 2662,257.54 2662,275 2662,278.75 2658.25,282.5 2653.75,282.5 2650,286.25 2650,293.75 2653.75,297.5 2662,297.5 2670.25,297.5 2674,301.25 2674,308.75 2670.25,312.5 2662,312.5 2653.75,312.5 2650,316.25 2650,323.75 2653.75,327.5 2662,327.5 2670.25,327.5 2674,331.25 2674,338.75 2670.25,342.5 2662,342.5 2653.75,342.5 2650,346.25 2650,353.75 2653.75,357.5 2662,357.5 2670.25,357.5 2674,361.25 2674,368.75 2670.25,372.5 2662,372.5 2653.75,372.5 2650,376.25 2650,383.75 2653.75,387.5 2662,387.5 2670.25,387.5 2674,391.25 2674,398.75 2670.25,402.5 2662,402.5 2653.75,402.5 2650,406.25 2650,413.75 2653.75,417.5 2662,417.5 2670.25,417.5 2674,421.25 2674,428.75 2670.25,432.5 2662,432.5 2653.75,432.5 2650,436.25 2650,443.75 2653.75,447.5 2662,447.5 2670.25,447.5 2674,451.25 2674,458.75 2670.25,462.5 2662,462.5 2653.75,462.5 2650,466.25 2650,473.75 2653.75,477.5 2662,477.5 2670.25,477.5 2674,481.25 2674,488.75 2670.25,492.5 2662,492.5 2653.75,492.5 2650,496.25 2650,503.75 2653.75,507.5 2662,507.5 2670.25,507.5 2674,511.25 2674,518.75 2670.25,522.5 2662,522.5 2653.75,522.5 2650,526.25 2650,533.75 2653.75,537.5 2662,537.5 2670.25,537.5 2674,541.25 2674,548.75 2670.25,552.5 2662,552.5 2653.75,552.5 2650,556.25 2650,563.75 2653.75,567.5 2662,567.5 2670.25,567.5 2674,571.25 2674,578.75 2670.25,582.5 2662,582.5 2653.75,582.5 2650,586.25 2650,593.75 2653.75,597.5 2662,597.5 2670.25,597.5 2674,601.25 2674,608.75 2670.25,612.5 2662,612.5 2653.75,612.5 2650,616.25 2650,623.75 2653.75,627.5 2662,627.5 2670.25,627.5 2674,631.25 2674,638.75 2670.25,642.5 2665.75,642.5 2662,646.25 2662,651 2662,659 2666,663 2668.65,665.65 2668.65,670.95 2667,672.6 2667,677.91 2672.31,683.21 2677.61,683.21 2681.91,678.91 2686.21,674.61 2691.51,674.61 2696.82,679.91 2696.82,685.22 2692.52,689.52 2688.22,693.82 2688.22,699.12 2693.52,704.42 2698.82,704.42 2703.12,700.12 2707.42,695.82 2712.73,695.82 2718.03,701.13 2718.03,706.43 2713.73,710.73 2709.43,715.03 2709.43,720.33 2714.73,725.64 2720.04,725.64 2724.34,721.34 2728.64,717.04 2733.94,717.04 2739.24,722.34 2739.24,727.64 2737.59,729.29 2737.59,734.59 2773,770 2815,812 2815,1095 v1(2789,1121)
  Top Layer w8: U4.19@714.95,258.2 714.95,227.05 730,212 v1(730,180) ; v1@728,179 v1@728,180
  Top Layer w15: U3.19@1612.22,256.62 v1@1612.22,291.78 ; v1(2409,127) U2.30@2455.91,127
  Signal Layer 3 w6: v1@728,179 728,138 741,125 743.65,122.35 748.95,122.35 775.46,148.85 780.76,148.85 786.07,143.55 786.07,138.25 756.91,109.09 719.42,71.6 719.42,66.3 724.73,61 730.03,61 767.52,98.48 796.67,127.64 801.98,127.64 807.28,122.34 807.28,117.03 778.12,87.88 761.85,71.61 761.85,66.3 767.15,61 772.46,61 786.08,74.62 791.38,74.62 799.34,66.66 805,61 812.5,61 823.75,61 827.5,64.75 827.5,87.12 831.25,90.87 838.75,90.87 842.5,87.12 842.5,64.75 846.25,61 852,61 1525,61 1530.3,66.3 1538.26,74.26 1543.56,74.26 1555.91,61.91 1561.21,61.91 1566.52,67.21 1566.52,72.52 1551.52,87.52 1536.52,102.52 1536.52,107.82 1541.82,113.12 1547.12,113.12 1562.12,98.12 1577.12,83.12 1582.43,83.12 1587.73,88.43 1587.73,93.73 1572.73,108.73 1557.73,123.73 1557.73,129.03 1563.03,134.34 1568.34,134.34 1583.34,119.34 1598.34,104.34 1603.64,104.34 1608.94,109.64 1608.94,114.94 1596.59,127.29 1596.59,132.59 1612,148 1612,297 1643,328 1717,328 1758,287 1758,284 1758,277.5 1758,266.25 1761.75,262.5 1776.25,262.5 1780,258.75 1780,251.25 1776.25,247.5 1758,247.5 1739.75,247.5 1736,243.75 1736,236.25 1739.75,232.5 1758,232.5 1776.25,232.5 1780,228.75 1780,221.25 1776.25,217.5 1758,217.5 1739.75,217.5 1736,213.75 1736,206.25 1739.75,202.5 1758,202.5 1776.25,202.5 1780,198.75 1780,191.25 1776.25,187.5 1758,187.5 1739.75,187.5 1736,183.75 1736,176.25 1739.75,172.5 1758,172.5 1776.25,172.5 1780,168.75 1780,161.25 1776.25,157.5 1758,157.5 1739.75,157.5 1736,153.75 1736,146.25 1739.75,142.5 1758,142.5 1776.25,142.5 1780,138.75 1780,131.25 1776.25,127.5 1758,127.5 1739.75,127.5 1736,123.75 1736,116.25 1739.75,112.5 1758,112.5 1776.25,112.5 1780,108.75 1780,101.25 1776.25,97.5 1758,97.5 1739.75,97.5 1736,93.75 1736,86.25 1739.75,82.5 1758,82.5 1776.25,82.5 1780,78.75 1780,71.25 1776.25,67.5 1761.75,67.5 1758,63.75 1758,52.5 1758,45 1767,36 1875.25,36 1891,51.75 1891,53.5 1891,64.75 1894.75,68.5 1909.25,68.5 1913,72.25 1913,79.75 1909.25,83.5 1891,83.5 1872.75,83.5 1869,87.25 1869,94.75 1872.75,98.5 1891,98.5 1909.25,98.5 1913,102.25 1913,109.75 1909.25,113.5 1891,113.5 1872.75,113.5 1869,117.25 1869,124.75 1872.75,128.5 1891,128.5 1909.25,128.5 1913,132.25 1913,139.75 1909.25,143.5 1891,143.5 1872.75,143.5 1869,147.25 1869,154.75 1872.75,158.5 1887.25,158.5 1891,162.25 1891,173.5 1891,181 1897,187 1906,187 1909.75,187 1913.5,190.75 1913.5,198.18 1917.25,201.93 1924.75,201.93 1928.5,198.18 1928.5,190.75 1932.25,187 1949,187 2007,187 2029,165 2075,165 2079,169 2356,169 2398,127 v1(2409,127)
  Bottom Layer w7: J1.9@2636.35,1236.74 2636.35,1170.65 2687,1120 2788,1120 v1(2789,1121)
  other v1: 1612,300
EM_A6: J1.11@2620.61,1236.74 U2.31 U3.20 U4.18 | length 6486.2
  Top Layer w6: v1@1643.72,216.72 1643.72,166 1628.72,151 1434,151 1422,139 1422,45 1441,26 2049,26 2179.04,156.04 2186.54,156.04 2197.79,156.04 2201.54,152.29 2201.54,136.71 2205.29,132.96 2212.79,132.96 2216.54,136.71 2216.54,156.04 2216.54,175.37 2220.29,179.12 2227.79,179.12 2231.54,175.37 2231.54,156.04 2231.54,136.71 2235.29,132.96 2242.79,132.96 2246.54,136.71 2246.54,156.04 2246.54,175.37 2250.29,179.12 2257.79,179.12 2261.54,175.37 2261.54,156.04 2261.54,136.71 2265.29,132.96 2272.79,132.96 2276.54,136.71 2276.54,156.04 2276.54,175.37 2280.29,179.12 2287.79,179.12 2291.54,175.37 2291.54,156.04 2291.54,136.71 2295.29,132.96 2302.79,132.96 2306.54,136.71 2306.54,156.04 2306.54,175.37 2310.29,179.12 2317.79,179.12 2321.54,175.37 2321.54,156.04 2321.54,136.71 2325.29,132.96 2332.79,132.96 2336.54,136.71 2336.54,156.04 2336.54,175.37 2340.29,179.12 2347.79,179.12 2351.54,175.37 2351.54,156.04 2351.54,136.71 2355.29,132.96 2362.79,132.96 2366.54,136.71 2366.54,156.04 2366.54,175.37 2370.29,179.12 2377.79,179.12 2381.54,175.37 2381.54,159.79 2385.29,156.04 2397,156.04 U2.31@2458.36,156.04
  Top Layer w8: v1(694,215) 695.27,216.27 U4.18@695.27,258.2
  Top Layer w15: v1@1643.72,216.72 U3.20@1643.72,256.62 ; U2.31@2458.36,156.04 v1@2499.04,156.04
  Signal Layer 3 w6: v1@695,218 695,200 695,188.9 691.6,185.5 573.12,185.5 569.72,182.1 569.72,171.9 573.12,168.5 695,168.5 706.88,168.5 710.28,165.1 710.28,154.9 706.88,151.5 695,151.5 599.55,151.5 596.14,148.1 596.14,137.9 599.55,134.5 691.6,134.5 695,131.1 695,126 695,122.25 698.75,118.5 716.42,118.5 720.17,114.75 720.17,107.25 716.42,103.5 695,103.5 658.95,103.5 655.2,99.75 655.2,92.25 658.95,88.5 691.25,88.5 695,84.75 695,57 704,48 1634,48 1643.72,57.72 v1@1643.72,216.72
  Bottom Layer w7: v1@2499.04,156.04 2473,156.04 2467.6,156.04 2464,152.44 2464,149.6 2460.4,146 2449.6,146 2446,149.6 2446,156.04 2446,167.44 2442.4,171.04 2431.6,171.04 2428,167.44 2428,156.04 2428,151.6 2424.4,148 2413.6,148 2410,151.6 2410,156.04 2410,164.01 2406.4,167.61 2395.6,167.61 2392,164.01 2392,156.04 2392,144.64 2388.4,141.04 2377.6,141.04 2374,144.64 2374,156.04 2374,167.44 2370.4,171.04 2359.6,171.04 2356,167.44 2356,156.04 2356,144.64 2352.4,141.04 2341.6,141.04 2338,144.64 2338,156.04 2338,167.44 2334.4,171.04 2323.6,171.04 2320,167.44 2320,156.04 2320,144.64 2316.4,141.04 2305.6,141.04 2302,144.64 2302,156.04 2302,167.44 2298.4,171.04 2287.6,171.04 2284,167.44 2284,156.04 2284,144.64 2280.4,141.04 2269.6,141.04 2266,144.64 2266,156.04 2266,167.44 2262.4,171.04 2251.6,171.04 2248,167.44 2248,156.04 2248,144.64 2244.4,141.04 2233.6,141.04 2230,144.64 2230,152.44 2226.4,156.04 2166,156.04 2153.96,156.04 2144,166 2144,178 2148,182 2152,182 2156,186 2156,194 2152,198 2144,198 2136,198 2132,202 2132,210 2136,214 2144,214 2152,214 2156,218 2156,226 2152,230 2144,230 2136,230 2132,234 2132,242 2136,246 2144,246 2152,246 2156,250 2156,258 2152,262 2144,262 2136,262 2132,266 2132,274 2136,278 2140,278 2144,282 2144,294 2144,302 2171,329 2172,329 2192,329 2196,333 2196,348.15 2200,352.15 2208,352.15 2212,348.15 2212,329 2212,309.85 2216,305.85 2224,305.85 2228,309.85 2228,329 2228,348.15 2232,352.15 2240,352.15 2244,348.15 2244,329 2244,309.85 2248,305.85 2256,305.85 2260,309.85 2260,329 2260,348.15 2264,352.15 2272,352.15 2276,348.15 2276,329 2276,309.85 2280,305.85 2288,305.85 2292,309.85 2292,329 2292,348.15 2296,352.15 2304,352.15 2308,348.15 2308,329 2308,309.85 2312,305.85 2320,305.85 2324,309.85 2324,325 2328,329 2332,329 2342,329 2485,472 2535,472 2665,602 2665,1116 2620.61,1160.39 J1.11@2620.61,1236.74
  other v1: 2503.04,156.04 1642.72,213.72
EM_A7: J1.12@2620.61,1329.26 U2.32 U3.21 U4.8 | length 6438.6
  Top Layer w8: v1@498,298 498.42,297.58 U4.8@498.42,258.2
  Top Layer w15: U3.21@1675.21,256.62 v1@1675.21,292.79 ; v1(2414.46,187.54) U2.32@2458.36,187.54
  Signal Layer 3 w6: v1@498,298 498,282 498,276.9 501.4,273.5 504.63,273.5 508.03,270.1 508.03,259.9 504.63,256.5 501.4,256.5 498,253.1 498,231 498,199 506.5,190.5 510.11,186.89 514.91,186.89 518.59,190.57 523.4,190.57 530.61,183.36 530.61,178.55 524.53,172.47 518.45,166.39 518.45,161.58 525.66,154.37 530.47,154.37 536.55,160.45 542.63,166.53 547.44,166.53 554.65,159.32 554.65,154.51 548.57,148.43 542.49,142.35 542.49,137.54 549.7,130.33 554.51,130.33 560.59,136.41 566.67,142.49 571.48,142.49 578.7,135.28 578.7,130.47 572.61,124.39 566.53,118.3 566.53,113.5 573.75,106.28 578.55,106.28 584.64,112.36 590.72,118.45 595.52,118.45 602.74,111.23 602.74,106.42 596.66,100.34 590.58,94.26 590.58,89.45 597.79,82.24 602.6,82.24 608.68,88.32 614.76,94.4 619.57,94.4 626.78,87.19 626.78,82.38 620.7,76.3 614.62,70.22 614.62,65.41 621.83,58.2 626.64,58.2 632.72,64.28 638.8,70.36 643.61,70.36 650.82,63.15 650.82,58.34 646.5,54.02 646.5,50.5 662,35 1660,35 1675.21,50.21 v1@1675.21,296.79
  Bottom Layer w6: v1@1675.21,296.79 1675.21,274.21 1664,263 1664,185 1629.5,150.5 1435.5,150.5 1425,140 1425,134 1425,128.75 1427.25,126.5 1431,122.75 1431,115.25 1427.25,111.5 1425,111.5 1422.75,111.5 1419,107.75 1419,100.25 1422.75,96.5 1425,96.5 1427.25,96.5 1431,92.75 1431,85.25 1427.25,81.5 1425,81.5 1422.75,81.5 1419,77.75 1419,70.25 1422.75,66.5 1425,64.25 1425,40 1441,24 1446.25,24 1448.5,26.25 1452.25,30 1459.75,30 1463.5,26.25 1463.5,24 1463.5,21.75 1467.25,18 1474.75,18 1478.5,21.75 1478.5,24 1478.5,26.25 1482.25,30 1489.75,30 1493.5,26.25 1493.5,24 1493.5,21.75 1497.25,18 1504.75,18 1508.5,21.75 1508.5,24 1508.5,26.25 1512.25,30 1519.75,30 1523.5,26.25 1523.5,24 1523.5,21.75 1527.25,18 1534.75,18 1538.5,21.75 1538.5,24 1538.5,26.25 1542.25,30 1549.75,30 1553.5,26.25 1553.5,24 1553.5,21.75 1557.25,18 1564.75,18 1568.5,21.75 1568.5,24 1568.5,26.25 1572.25,30 1579.75,30 1583.5,26.25 1583.5,24 1583.5,21.75 1587.25,18 1594.75,18 1598.5,21.75 1598.5,24 1598.5,26.25 1602.25,30 1609.75,30 1613.5,26.25 1613.5,24 1613.5,21.75 1617.25,18 1624.75,18 1628.5,21.75 1628.5,24 1628.5,26.25 1632.25,30 1639.75,30 1643.5,26.25 1645.75,24 1723,24 2465,24 2569,128 2569,187 2514,242 2488,242 2433.54,187.54 v1(2414.46,187.54) 2195.46,187.54 2186,197 2186,244 2208,266 2326,266 2405,345 2428,345 2446,363 2446,393 2502,449 2548,449 2718,619 2718,665 2718,692.75 2721.75,696.5 2729.58,696.5 2733.33,700.25 2733.33,707.75 2729.58,711.5 2718,711.5 2706.42,711.5 2702.67,715.25 2702.67,722.75 2706.42,726.5 2718,726.5 2729.58,726.5 2733.33,730.25 2733.33,737.75 2729.58,741.5 2718,741.5 2706.42,741.5 2702.67,745.25 2702.67,752.75 2706.42,756.5 2718,756.5 2729.58,756.5 2733.33,760.25 2733.33,767.75 2729.58,771.5 2718,771.5 2706.42,771.5 2702.67,775.25 2702.67,782.75 2706.42,786.5 2718,786.5 2729.58,786.5 2733.33,790.25 2733.33,797.75 2729.58,801.5 2718,801.5 2706.42,801.5 2702.67,805.25 2702.67,812.75 2706.42,816.5 2718,816.5 2729.58,816.5 2733.33,820.25 2733.33,827.75 2729.58,831.5 2718,831.5 2706.42,831.5 2702.67,835.25 2702.67,842.75 2706.42,846.5 2718,846.5 2729.58,846.5 2733.33,850.25 2733.33,857.75 2729.58,861.5 2718,861.5 2706.42,861.5 2702.67,865.25 2702.67,872.75 2706.42,876.5 2718,876.5 2729.58,876.5 2733.33,880.25 2733.33,887.75 2729.58,891.5 2718,891.5 2706.42,891.5 2702.67,895.25 2702.67,902.75 2706.42,906.5 2718,906.5 2729.58,906.5 2733.33,910.25 2733.33,917.75 2729.58,921.5 2721.75,921.5 2718,925.25 2718,929 2718,1017 2851.5,1150.5 2851.5,1328.5 2786,1394 2653.61,1394 2620.61,1361 J1.12@2620.61,1329.26
  other v1: 1675.21,299.79 498,302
